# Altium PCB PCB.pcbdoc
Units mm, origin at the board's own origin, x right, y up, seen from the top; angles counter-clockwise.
Board outline 44.52 x 42.7 mm, 2 copper layers (Top Layer, Bottom Layer); 13 components, 6 nets, 30 pads, 10 vias.
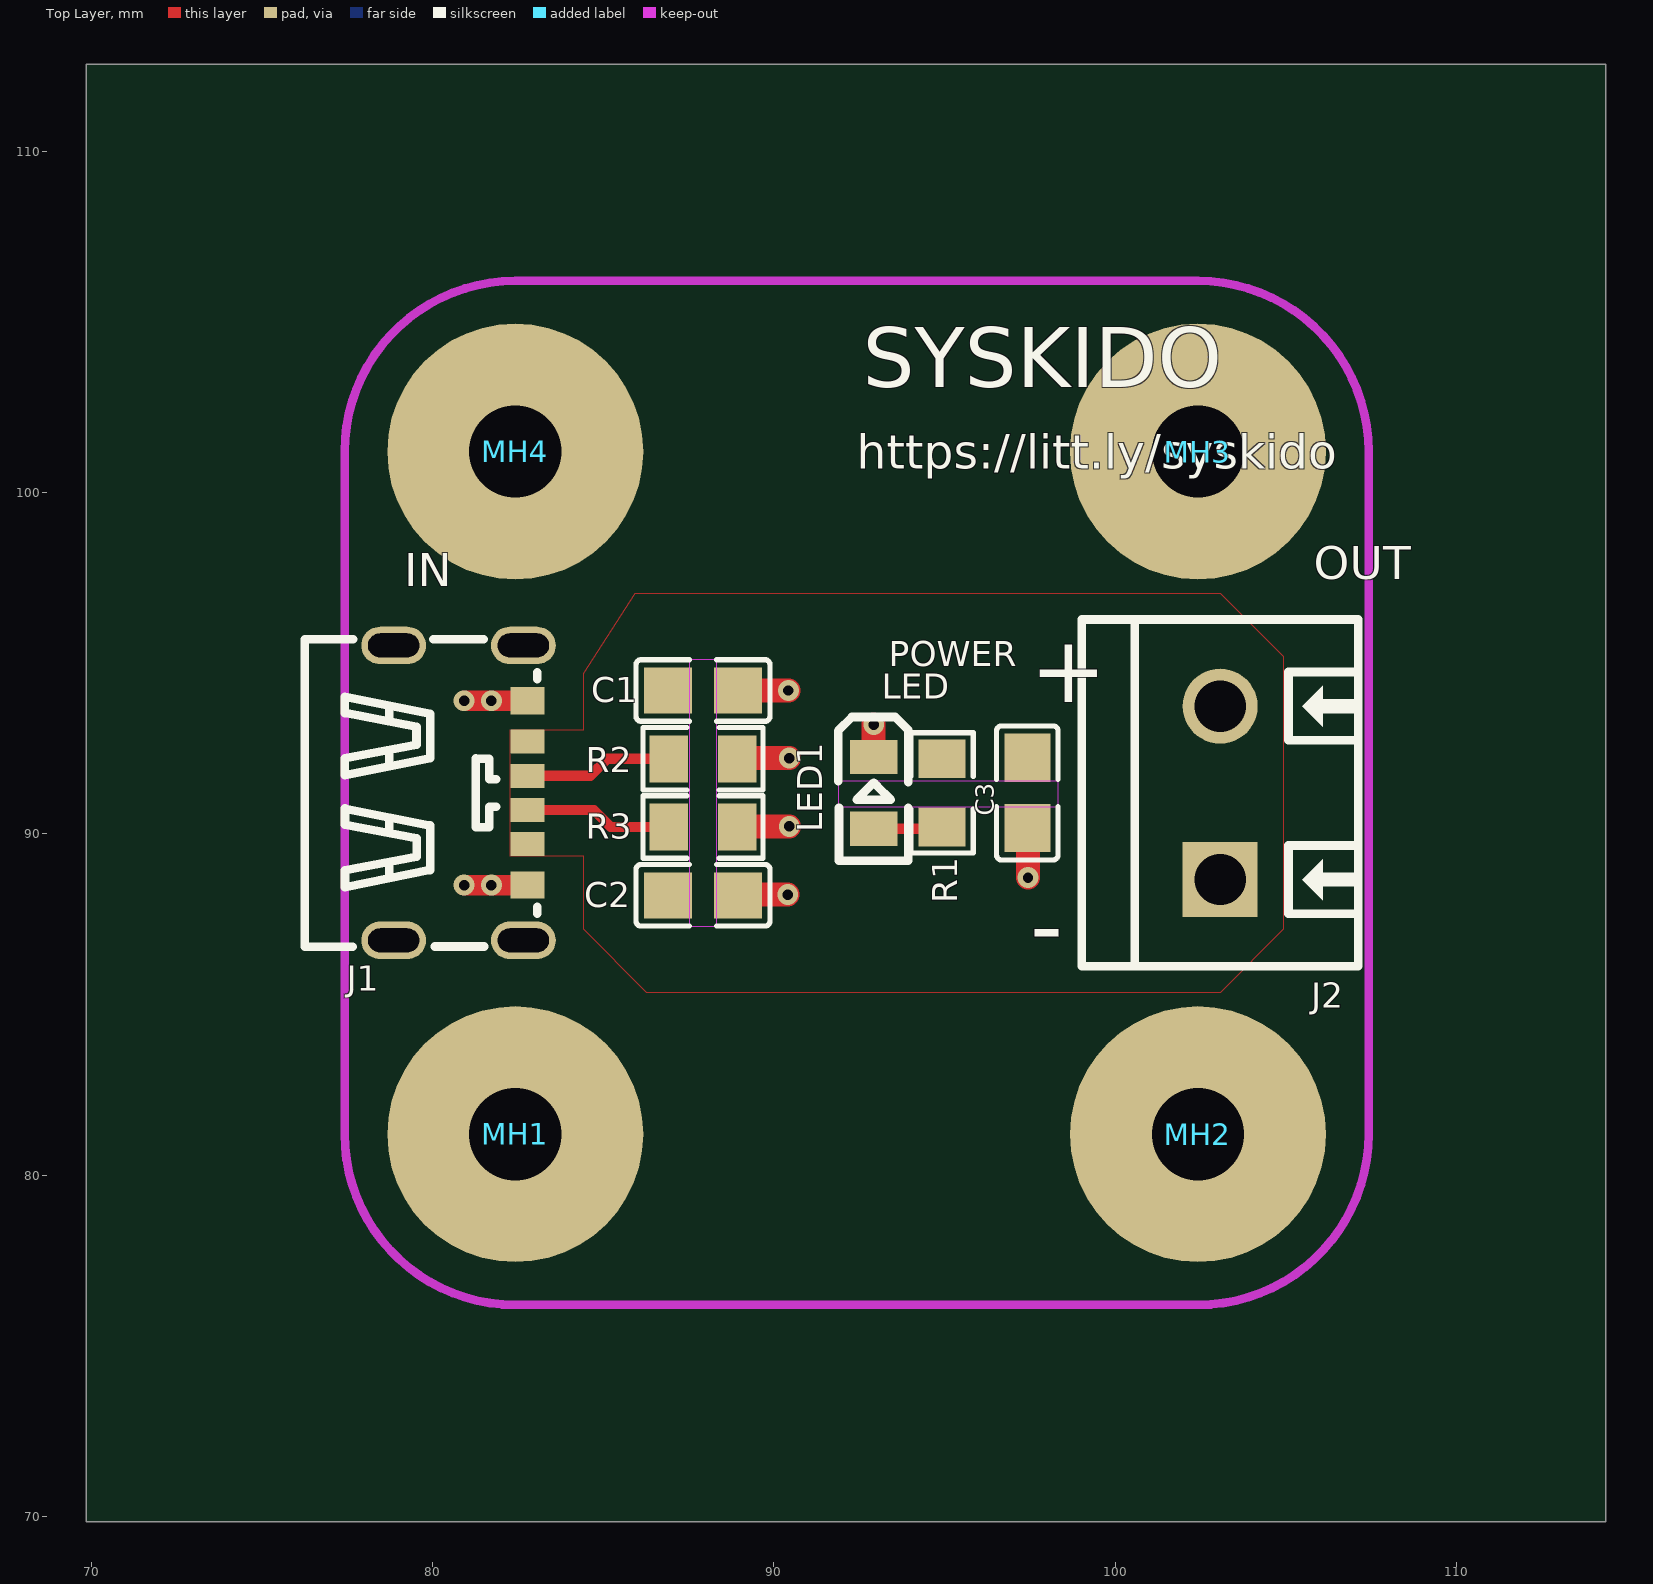
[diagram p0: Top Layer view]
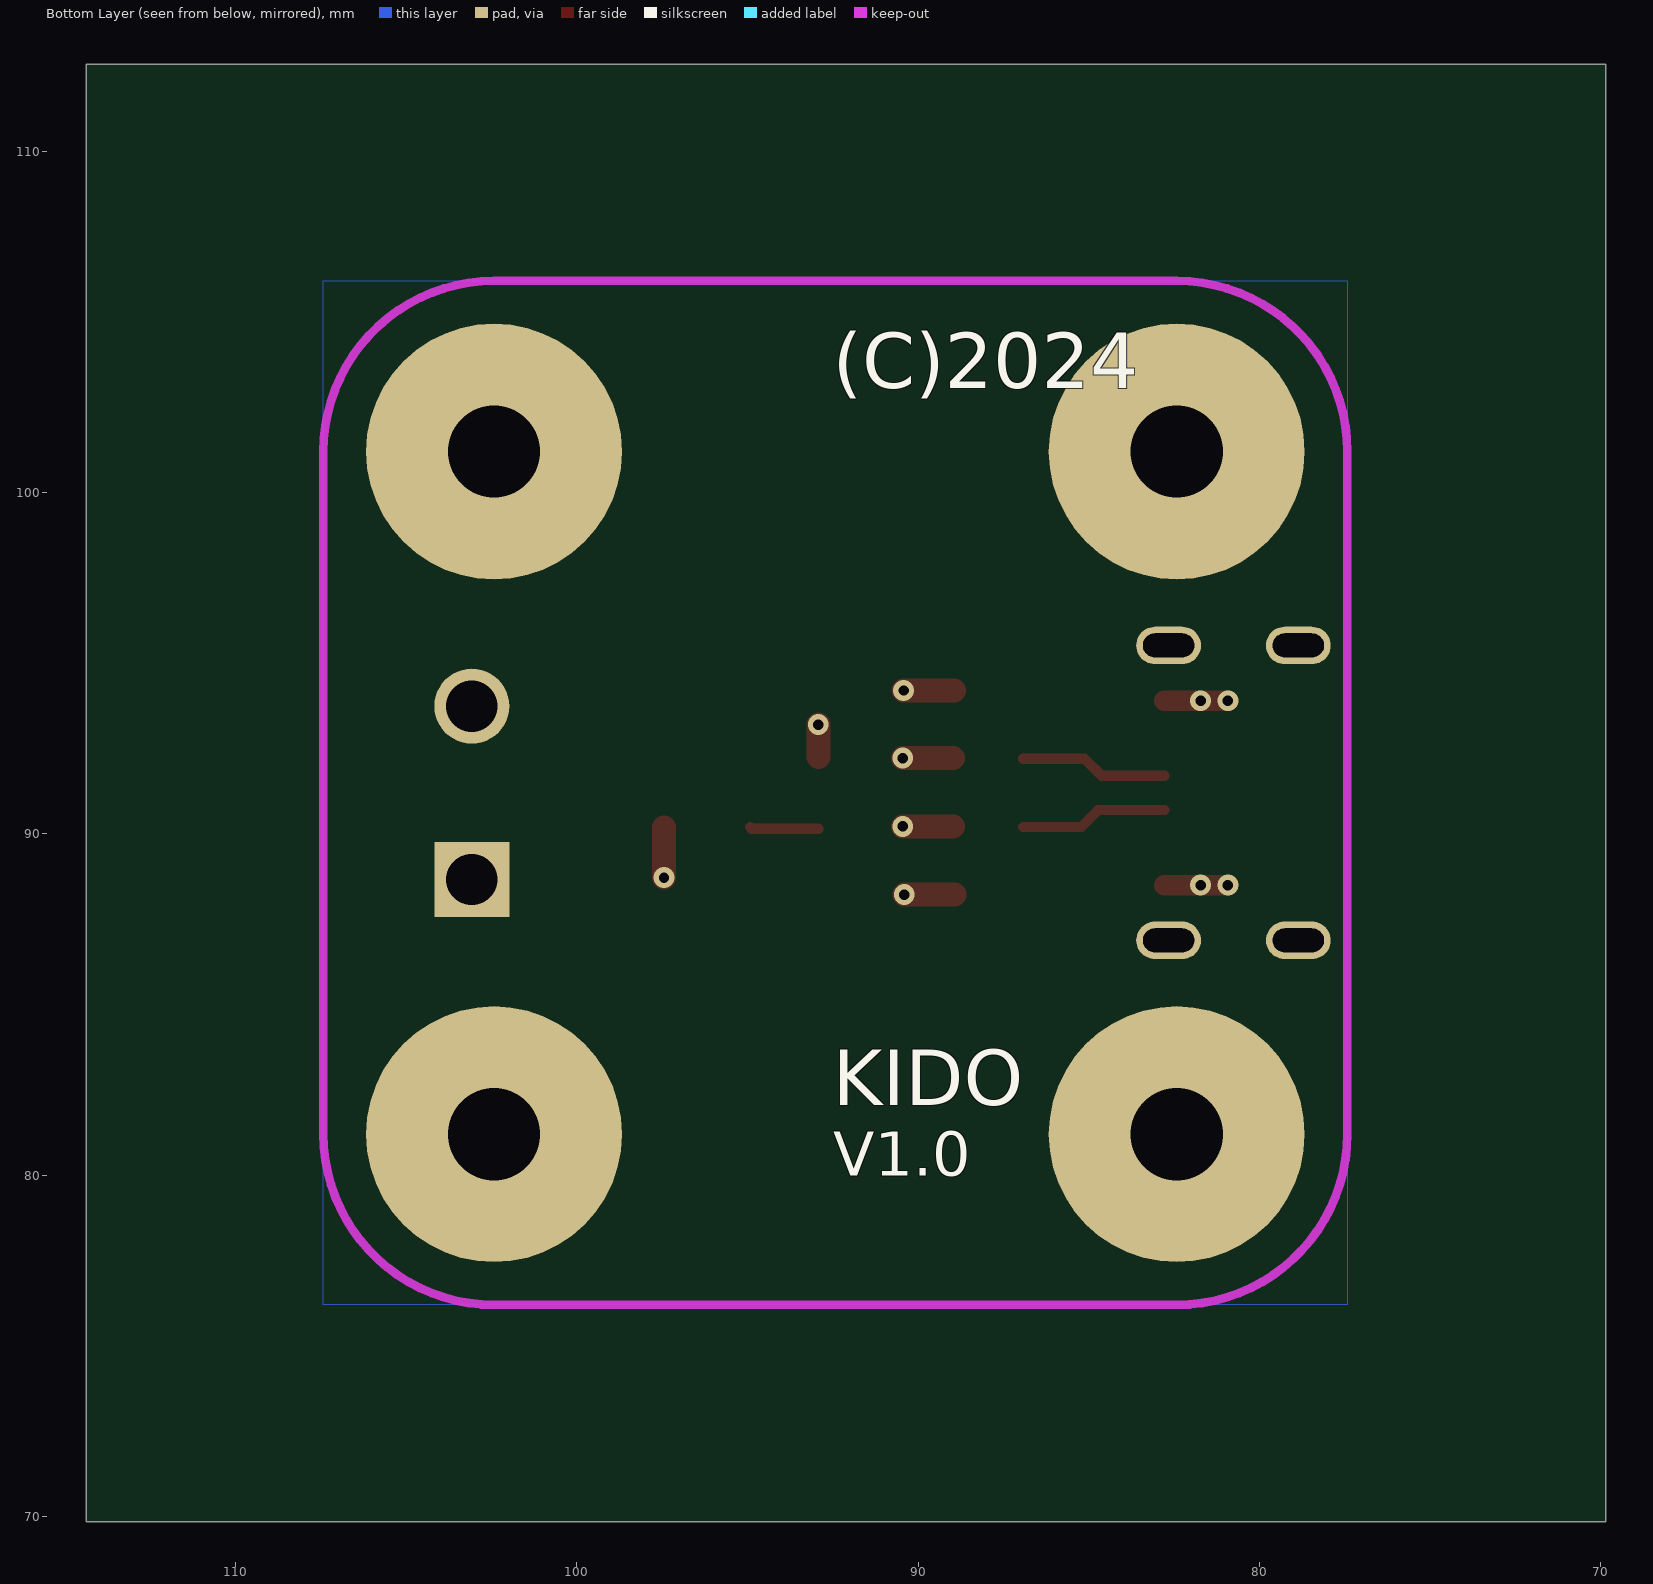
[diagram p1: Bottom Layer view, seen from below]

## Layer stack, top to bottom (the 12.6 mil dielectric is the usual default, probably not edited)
Top Layer: signal copper (thickness not stored)
Dielectric: dielectric 0.32, FR-4, Dk 4.8
Bottom Layer: signal copper (thickness not stored)

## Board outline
114.372,69.85 69.85,69.85 69.85,112.55 114.372,112.55

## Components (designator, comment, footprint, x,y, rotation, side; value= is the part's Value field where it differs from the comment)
C1 "CC0805KRX7R9BB104" C0805 87.922,94.2 r180 top
C2 "CC0805KRX7R9BB104" C0805 87.922,88.2 r180 top
C3 "CC0805KRX7R9BB104" C0805 97.422,91.2 r90 top
J1 "TYPE-C 6P(073)" TYPE-C-SMD_TYPE-C-6P 80.822,91.2 r270 top
J2 "MKDSN 1,5/ 2-5,08" CONN-TH_2P-P5.08_1729128 103.072,91.2 r90 top
LED1 "KT-0805G" LED0805-R-RD 92.922,91.2 r270 top
MH1 "MH_7.5x2.7MM" MH_7.5X2.7MM 82.422,81.2 r0 top
MH2 "MH_7.5x2.7MM" MH_7.5X2.7MM 102.422,81.2 r0 top
MH3 "MH_7.5x2.7MM" MH_7.5X2.7MM 102.422,101.2 r0 top
MH4 "MH_7.5x2.7MM" MH_7.5X2.7MM 82.422,101.2 r0 top
R1 "0805W8F1001T5E" R0805 94.922,91.2 r90 top
R2 "0805W8F5101T5E" R0805 87.922,92.2 r180 top
R3 "0805W8F5101T5E" R0805 87.922,90.2 r180 top

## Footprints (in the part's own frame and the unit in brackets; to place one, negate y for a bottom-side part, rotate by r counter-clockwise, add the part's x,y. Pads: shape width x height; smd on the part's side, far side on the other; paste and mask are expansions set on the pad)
C0805 [mm]
  rect 1.41x1.35 smd: 1(-1.03,0) 2(1.03,0)
  silkscreen extent -1.96,-0.9 1.96,0.9
CONN-TH_2P-P5.08_1729128 [mm]
  rect 2.2x2.2 hole 1.5: 1(-2.54,0)
  round 2.2 hole 1.5: 2(2.54,0)
  silkscreen extent -5.08,-4.05 5.08,4.05
LED0805-R-RD [mm]
  rect 1x1.4 smd: 1(1.05,0) 2(-1.05,0)
  silkscreen extent -2.22,-1.04 1.99,1.01
MH_7.5X2.7MM [mm]
  round 7.5 hole 2.7: 1(0,0)
R0805 [mm]
  rect 1.133x1.377 smd: 1(-1,0) 2(1,0)
  silkscreen extent -1.76,-0.92 1.76,0.92
TYPE-C-SMD_TYPE-C-6P [mm]
  oval 1.1x1.9 hole 0.7 slot 1.5 at 90 deg: 7(-4.32,-1.963) 7(-4.32,1.838) 7(4.32,-1.963) 7(4.32,1.838)
  rect 0.7x1 smd: A5(-0.5,1.963) A9(1.5,1.963) B5(0.5,1.963) B9(-1.5,1.963)
  rect 0.8x1 smd: A12(2.7,1.963) B12(-2.7,1.963)
  silkscreen extent -4.5,-4.56 4.5,2.24

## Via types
v1: diameter 0.61, hole 0.305, Top Layer to Bottom Layer, 10 vias

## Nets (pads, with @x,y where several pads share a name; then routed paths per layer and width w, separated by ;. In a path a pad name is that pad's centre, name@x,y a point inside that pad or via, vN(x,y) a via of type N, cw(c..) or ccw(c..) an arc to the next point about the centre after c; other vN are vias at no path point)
+5V: C1.2 C2.2 C3.2 J1.A9 J1.B9 J2.1 J2.2 LED1.2 R1.2 | length 0.9
  Top Layer w0.7: LED1.2 92.922,93.2
CC1: J1.B5 R3.2 | length 4.3
  Top Layer w0.3: J1.B5 84.722,90.7 85.222,90.2 R3.2
CC2: J1.A5 R2.2 | length 4.3
  Top Layer w0.3: J1.A5 84.622,91.7 85.122,92.2 R2.2
DIODE: LED1.1 R1.1 | length 2
  Top Layer w0.3: LED1.1 94.872,90.15 R1.1
GND: C3.1 J1.7 J1.A12 J1.B12 MH1.1 MH2.1 MH3.1 MH4.1 R2.1 R3.1 | length 8.1
  Top Layer w0.6: v1(80.922,88.5) 81.809,88.5 J1.A12 ; v1(80.922,93.9) 81.809,93.9 J1.B12
  Top Layer w0.7: R3.1@88.977,90.22 v1(90.447,90.22) ; R2.1@88.977,92.22 v1(90.447,92.22) ; v1(97.442,88.718) C3.1@97.442,90.188
  other v1: 90.405,88.22 81.722,88.5 92.922,93.2 81.722,93.9 90.422,94.2
"": C1.1 C2.1 | length 2.9
  Top Layer w0.7: C2.1@88.935,88.22 90.405,88.22 ; C1.1 90.422,94.2

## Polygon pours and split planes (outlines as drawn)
GND on Bottom Layer (solid, remove dead copper, pour order 0): 77.422,76.2 107.422,76.2 107.422,106.2 77.422,106.2
+5V on Top Layer (solid, remove dead copper, pour order 1): 84.422,94.7 85.941,97.05 103.072,97.05 104.922,95.2 104.922,87.2 103.072,85.35 86.272,85.35 84.422,87.2 84.422,89.35 82.272,89.35 82.272,93.05 84.422,93.05

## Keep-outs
Top Layer:
  region net "": 87.521,87.296 88.324,87.296 88.324,95.104 87.521,95.104
  region net "": 91.88,90.799 98.326,90.799 98.326,91.544 91.88,91.544
Board Outline Layer:
  lines w0.254 net "": 77.422,81.2 ccw(c82.422,81.2) 82.422,76.2 102.422,76.2 ccw(c102.422,81.2) 107.422,81.2 107.422,101.2 ccw(c102.422,101.2) 102.422,106.2 82.422,106.2 ccw(c82.422,101.2) 77.422,101.2 77.422,81.2

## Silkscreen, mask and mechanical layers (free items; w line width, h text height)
Top Silkscreen Layer:
  text "SYSKIDO" at 92.604,103.077 h1.75
  text "https://litt.ly/syskido" at 92.422,100.7 h1
  text "OUT" at 105.818,97.459 h0.97
  text "IN" at 79.168,97.259 h0.97
  text "POWER" at 93.357,94.904 h0.74
  text "LED" at 93.157,93.954 h0.74
  text "+" at 97.515,93.859 h1.96
  text "-" at 97.515,86.359 h1.96
Bottom Silkscreen Layer:
  text "(C)2024" at 92.498,103.049 h1.62
  text "KIDO" at 92.498,82.049 h1.62
  text "V1.0" at 92.483,79.979 h1.3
